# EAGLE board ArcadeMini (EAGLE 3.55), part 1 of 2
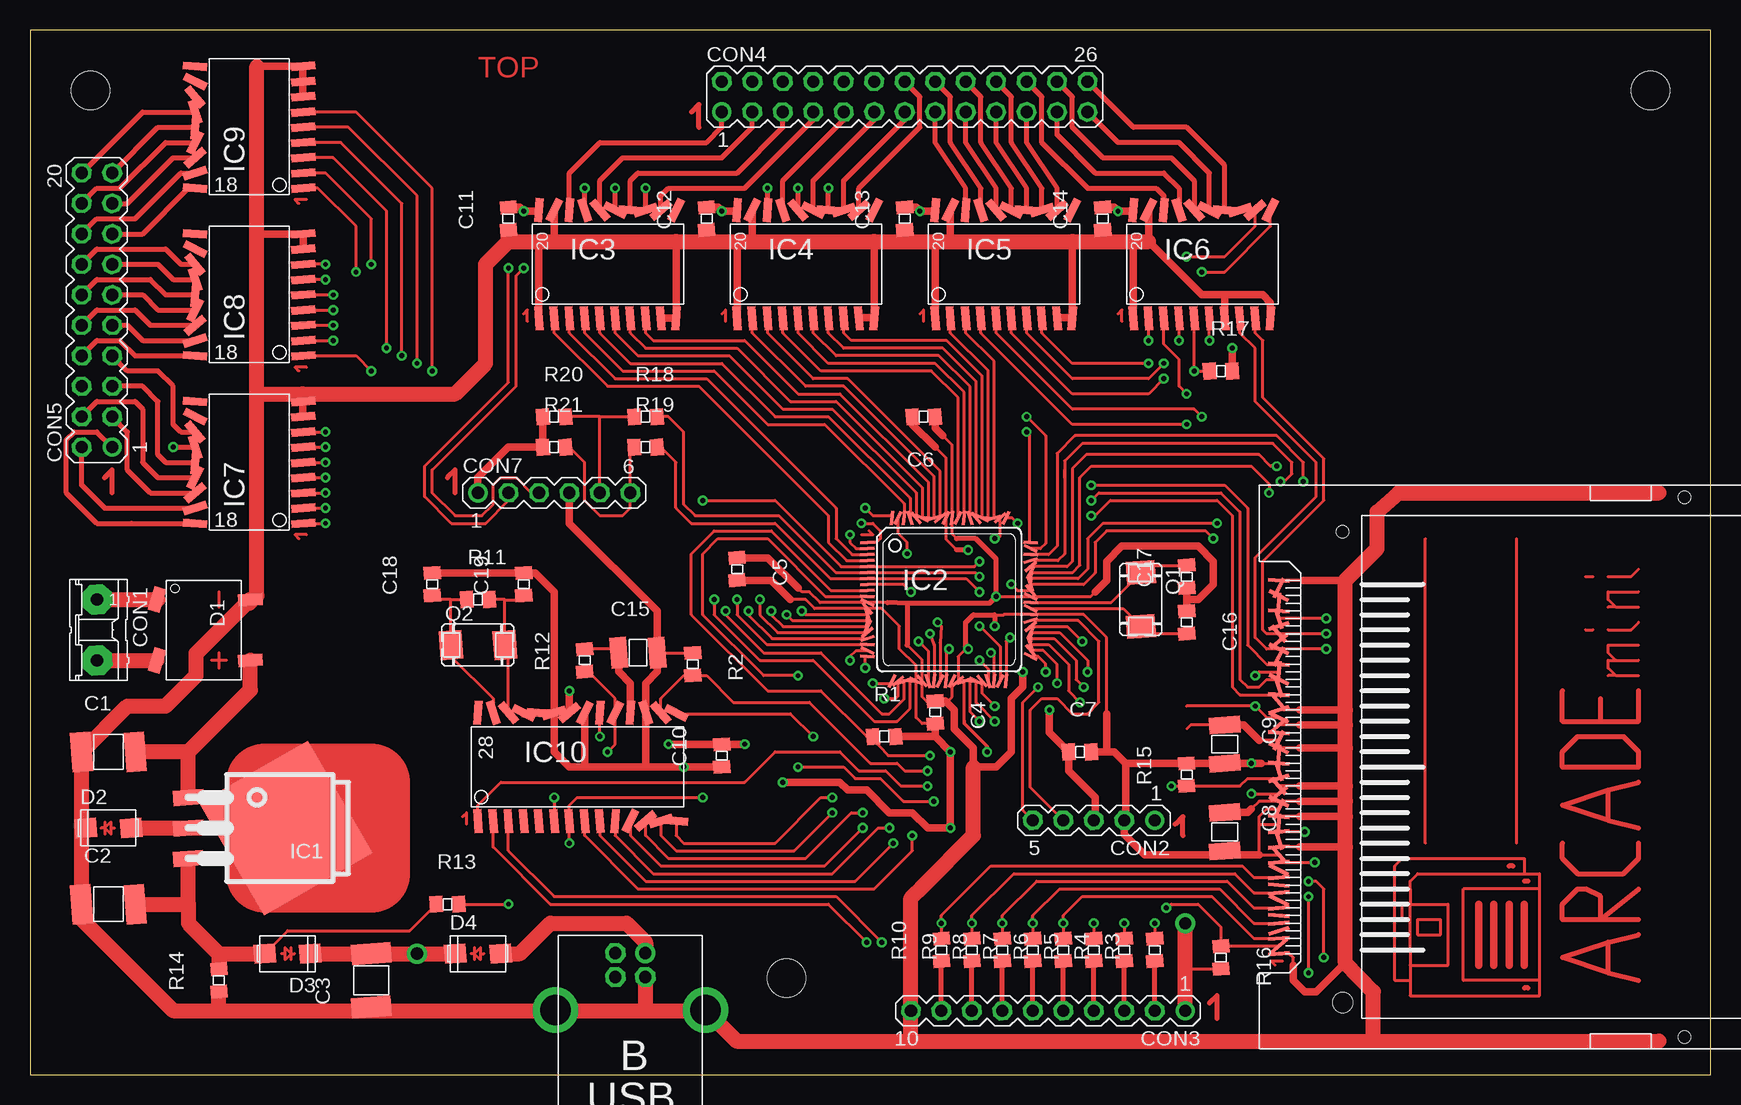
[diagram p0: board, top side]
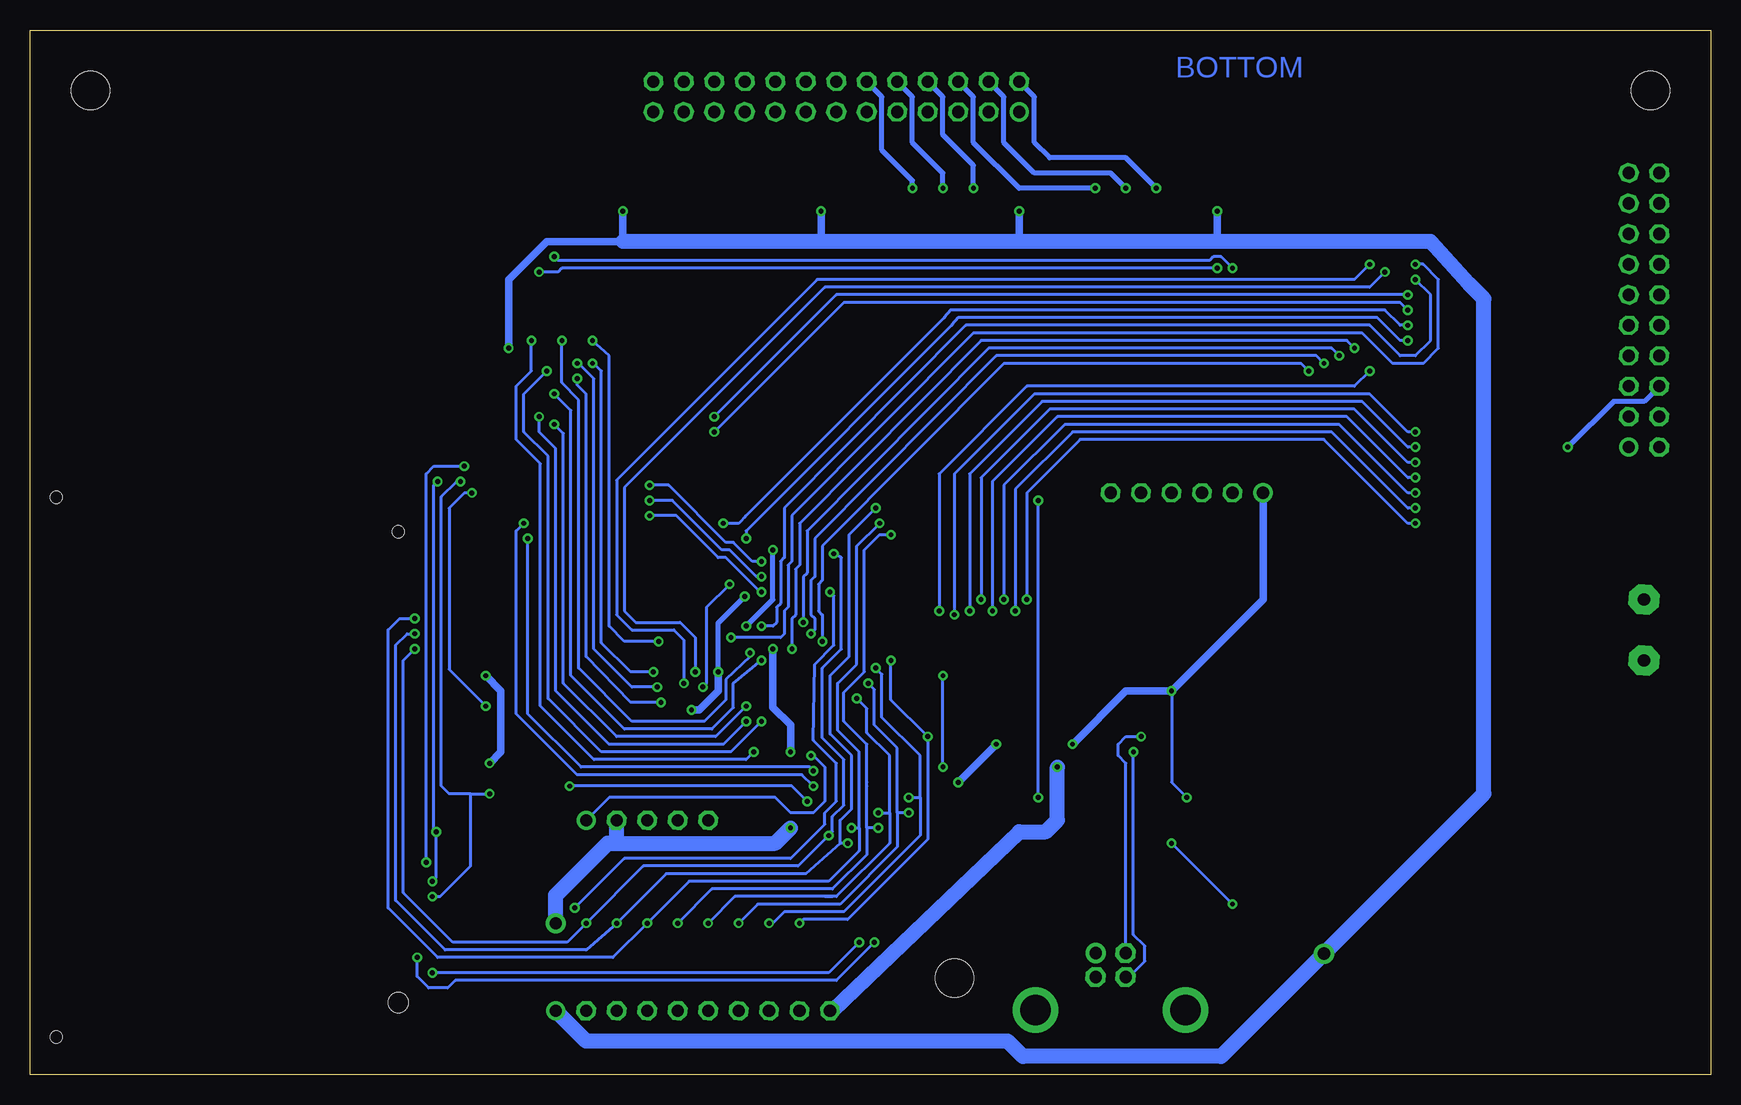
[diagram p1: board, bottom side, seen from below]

Size 140.08 x 87.12 mm. Coordinates in mm from the lower left corner, seen from the top.
Outline: 0,0 140.08,0 140.08,87.12 0,87.12 0,0
Copper layers used: Top, Bottom
Holes 3.2 mm at 5.04,82.08 135.04,82.08 63.04,8.08

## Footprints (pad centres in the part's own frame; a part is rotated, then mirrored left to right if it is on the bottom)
D-1812 = smd 1.702 x 3.302 rotated 4.4:  2.235,0 | smd 1.702 x 3.302 rotated 4.3:  -2.235,0
D-0805 = smd 1.092 x 1.397 rotated 4.4:  0.94,0 | smd 1.092 x 1.397 rotated 4.3:  -0.94,0
D-1210 = smd 1.397 x 2.591 rotated 4.4:  1.6,0 | smd 1.397 x 2.591 rotated 4.3:  -1.6,0
-FRM = smd 0.305 x 1.778 rotated 71.8:  -0.318,0.572 | smd 0.305 x 1.778 rotated 162:  -0.953,0.572 | smd 0.305 x 1.778 rotated 49.3:  -1.587,0.572 | smd 0.305 x 1.778 rotated 139.5:  -2.223,0.572 | smd 0.305 x 1.778 rotated 26.8:  -2.857,0.572 | smd 0.305 x 1.778 rotated 117:  -3.493,0.572 | smd 0.305 x 1.778 rotated 4.3:  -4.128,0.572;  -15.557,0.572 | smd 0.305 x 1.778 rotated 94.5:  -4.763,0.572 | smd 0.305 x 1.778 rotated 5:  -5.397,0.572 | smd 0.305 x 1.778 rotated 72:  -6.032,0.572 | smd 0.305 x 1.778 rotated 4.9:  -6.668,0.572 | smd 0.305 x 1.778 rotated 49.5:  -7.303,0.572 | smd 0.305 x 1.778 rotated 4.8:  -7.938,0.572 | smd 0.305 x 1.778 rotated 27:  -8.572,0.572 | smd 0.305 x 1.778 rotated 4.7:  -9.207,0.572;  -10.477,0.572;  15.557,0.572 | smd 0.305 x 1.778 rotated 4.5:  -9.842,0.572;  -13.018,0.572 | smd 0.305 x 1.778 rotated 206.9:  -11.113,0.572 | smd 0.305 x 1.778 rotated 4.6:  -11.748,0.572;  2.857,0.572 | smd 0.305 x 1.778 rotated 184.4:  -12.383,0.572 | smd 0.305 x 1.778 rotated 161.9:  -13.652,0.572 | smd 0.305 x 1.778 rotated 4.4:  -14.287,0.572;  8.572,0.572 | smd 0.305 x 1.778 rotated 139.4:  -14.922,0.572 | smd 0.305 x 1.778 rotated 116.9:  14.922,0.572 | smd 0.305 x 1.778 rotated 207.1:  14.287,0.572 | smd 0.305 x 1.778 rotated 94.4:  13.652,0.572 | smd 0.305 x 1.778 rotated 184.6:  13.018,0.572 | smd 0.305 x 1.778 rotated 71.9:  12.383,0.572 | smd 0.305 x 1.778 rotated 162.1:  11.748,0.572 | smd 0.305 x 1.778 rotated 49.4:  11.113,0.572 | smd 0.305 x 1.778 rotated 139.6:  10.477,0.572 | smd 0.305 x 1.778 rotated 26.9:  9.842,0.572 | smd 0.305 x 1.778 rotated 117.1:  9.207,0.572 | smd 0.305 x 1.778 rotated 94.6:  7.938,0.572 | smd 0.305 x 1.778 rotated 206.8:  7.303,0.572 | smd 0.305 x 1.778 rotated 72.1:  6.668,0.572 | smd 0.305 x 1.778 rotated 184.3:  6.032,0.572 | smd 0.305 x 1.778 rotated 49.6:  5.397,0.572 | smd 0.305 x 1.778 rotated 161.8:  4.763,0.572 | smd 0.305 x 1.778 rotated 27.1:  4.128,0.572 | smd 0.305 x 1.778 rotated 139.3:  3.493,0.572 | smd 0.305 x 1.778 rotated 116.8:  2.223,0.572 | smd 0.305 x 1.778 rotated 207:  1.587,0.572 | smd 0.305 x 1.778 rotated 94.3:  0.953,0.572 | smd 0.305 x 1.778 rotated 184.5:  0.318,0.572 | hole 1.676: -19.625,-4.75 | hole 1.016: 19.625,-4.75; 22.5,-33.25; -22.5,-33.25
N-BIG2 = drill 1.016 pad 2.54 octagon:  -2.54,0;  2.54,0
N-5-1 = drill 1.016 pad 1.6 round:  -5.08,0 | drill 1.016 pad 1.6 octagon:  -2.54,0;  0,0;  2.54,0;  5.08,0
N-10-1 = drill 1.016 pad 1.6 round:  -11.43,0 | drill 1.016 pad 1.6 octagon:  -8.89,0;  -6.35,0;  -3.81,0;  -1.27,0;  1.27,0;  3.81,0;  6.35,0;  8.89,0;  11.43,0
N-13-2 = drill 1.016 pad 1.6 round:  -15.24,-1.27 | drill 1.016 pad 1.6 octagon:  -12.7,-1.27;  -10.16,-1.27;  -7.62,-1.27;  -5.08,-1.27;  -2.54,-1.27;  -15.24,1.27;  -12.7,1.27;  -10.16,1.27;  -7.62,1.27;  -5.08,1.27;  -2.54,1.27;  0,-1.27;  0,1.27;  2.54,-1.27;  5.08,-1.27;  7.62,-1.27;  10.16,-1.27;  12.7,-1.27;  15.24,-1.27;  2.54,1.27;  5.08,1.27;  7.62,1.27;  10.16,1.27;  12.7,1.27;  15.24,1.27
N-10-2 = drill 1.016 pad 1.6 round:  -11.43,-1.27 | drill 1.016 pad 1.6 octagon:  -8.89,-1.27;  -6.35,-1.27;  -3.81,-1.27;  -1.27,-1.27;  1.27,-1.27;  -11.43,1.27;  -8.89,1.27;  -6.35,1.27;  -3.81,1.27;  -1.27,1.27;  1.27,1.27;  3.81,-1.27;  6.35,-1.27;  3.81,1.27;  6.35,1.27;  8.89,-1.27;  8.89,1.27;  11.43,-1.27;  11.43,1.27
B-B = drill 1.016 pad 1.676 octagon:  1.25,-1;  -1.25,1;  1.25,1 | drill 1.016 pad 1.676 round:  -1.25,-1 | drill 2.54 pad 3.81 round:  6.25,3.75;  -6.25,3.75
N-6-1 = drill 1.016 pad 1.6 round:  -6.35,0 | drill 1.016 pad 1.6 octagon:  -3.81,0;  -1.27,0;  1.27,0;  6.35,0;  3.81,0
64RECT = smd 1.016 x 2.032 rotated 4:  -2.515,3.886 | smd 1.016 x 2.032 rotated 3.8:  2.54,3.886 | smd 1.016 x 2.032 rotated 73.2:  2.54,-3.886;  -2.54,-3.886
A = smd 1.8 x 1.6 rotated 4.3:  -1.9,0 | smd 1.8 x 1.6 rotated 4.4:  1.9,0
-263 = smd 2.54 x 1.27 rotated 4.4:  -1.27,0 | smd 2.54 x 1.27 rotated 4.5:  -1.27,2.54 | smd 2.54 x 1.27 rotated 4.3:  -1.27,-2.54 | smd 10.414 x 10.795 rotated 29.9:  -9.398,0
FP-80 = smd 0.25 x 1.2 rotated 26.9:  -4.75,-6.8 | smd 0.25 x 1.2 rotated 49.4:  -4.25,-6.8 | smd 0.25 x 1.2 rotated 71.9:  -3.75,-6.8 | smd 0.25 x 1.2 rotated 94.4:  -3.25,-6.8 | smd 0.25 x 1.2 rotated 116.9:  -2.75,-6.8 | smd 0.25 x 1.2 rotated 139.4:  -2.25,-6.8 | smd 0.25 x 1.2 rotated 161.9:  -1.75,-6.8 | smd 0.25 x 1.2 rotated 184.4:  -1.25,-6.8 | smd 0.25 x 1.2 rotated 206.9:  -0.75,-6.8 | smd 0.25 x 1.2 rotated 4.5:  -0.25,-6.8 | smd 0.25 x 1.2 rotated 27:  0.25,-6.8 | smd 0.25 x 1.2 rotated 49.5:  0.75,-6.8 | smd 0.25 x 1.2 rotated 72:  1.25,-6.8 | smd 0.25 x 1.2 rotated 94.5:  1.75,-6.8 | smd 0.25 x 1.2 rotated 117:  2.25,-6.8 | smd 0.25 x 1.2 rotated 139.5:  2.75,-6.8 | smd 0.25 x 1.2 rotated 162:  3.25,-6.8 | smd 0.25 x 1.2 rotated 184.5:  3.75,-6.8 | smd 0.25 x 1.2 rotated 207:  4.25,-6.8 | smd 0.25 x 1.2 rotated 4.6:  4.75,-6.8 | smd 1.2 x 0.25 rotated 27.1:  6.8,-4.75 | smd 1.2 x 0.25 rotated 49.6:  6.8,-4.25 | smd 1.2 x 0.25 rotated 72.1:  6.8,-3.75 | smd 1.2 x 0.25 rotated 94.6:  6.8,-3.25 | smd 1.2 x 0.25 rotated 117.1:  6.8,-2.75 | smd 1.2 x 0.25 rotated 139.6:  6.8,-2.25 | smd 1.2 x 0.25 rotated 162.1:  6.8,-1.75 | smd 1.2 x 0.25 rotated 184.6:  6.8,-1.25 | smd 1.2 x 0.25 rotated 207.1:  6.8,-0.75 | smd 1.2 x 0.25 rotated 4.7:  6.8,-0.25;  6.8,4.75;  -6.8,2.75;  -6.8,2.25 | smd 1.2 x 0.25 rotated 27.2:  6.8,0.25 | smd 1.2 x 0.25 rotated 49.7:  6.8,0.75 | smd 1.2 x 0.25 rotated 72.2:  6.8,1.25 | smd 1.2 x 0.25 rotated 94.7:  6.8,1.75 | smd 1.2 x 0.25 rotated 117.2:  6.8,2.25 | smd 1.2 x 0.25 rotated 139.7:  6.8,2.75 | smd 1.2 x 0.25 rotated 162.2:  6.8,3.25 | smd 1.2 x 0.25 rotated 184.7:  6.8,3.75 | smd 1.2 x 0.25 rotated 207.2:  6.8,4.25 | smd 1.2 x 0.25 rotated 4.3:  -6.8,4.75;  -6.8,0.25 | smd 1.2 x 0.25 rotated 4.4:  -6.8,4.25;  -6.8,-4.75 | smd 1.2 x 0.25 rotated 4.5:  -6.8,3.75 | smd 1.2 x 0.25 rotated 4.6:  -6.8,3.25 | smd 1.2 x 0.25 rotated 4.8:  -6.8,1.75 | smd 1.2 x 0.25 rotated 4.9:  -6.8,1.25 | smd 1.2 x 0.25 rotated 5:  -6.8,0.75 | smd 1.2 x 0.25 rotated 26.8:  -6.8,-0.25 | smd 1.2 x 0.25 rotated 49.3:  -6.8,-0.75 | smd 1.2 x 0.25 rotated 71.8:  -6.8,-1.25 | smd 1.2 x 0.25 rotated 94.3:  -6.8,-1.75 | smd 1.2 x 0.25 rotated 116.8:  -6.8,-2.25 | smd 1.2 x 0.25 rotated 139.3:  -6.8,-2.75 | smd 1.2 x 0.25 rotated 161.8:  -6.8,-3.25 | smd 1.2 x 0.25 rotated 184.3:  -6.8,-3.75 | smd 1.2 x 0.25 rotated 206.8:  -6.8,-4.25 | smd 0.25 x 1.2 rotated 27.2:  4.75,6.8 | smd 0.25 x 1.2 rotated 49.7:  4.25,6.8 | smd 0.25 x 1.2 rotated 72.2:  3.75,6.8 | smd 0.25 x 1.2 rotated 94.7:  3.25,6.8 | smd 0.25 x 1.2 rotated 117.2:  2.75,6.8 | smd 0.25 x 1.2 rotated 139.7:  2.25,6.8 | smd 0.25 x 1.2 rotated 162.2:  1.75,6.8 | smd 0.25 x 1.2 rotated 184.7:  1.25,6.8 | smd 0.25 x 1.2 rotated 207.2:  0.75,6.8 | smd 0.25 x 1.2 rotated 4.8:  0.25,6.8 | smd 0.25 x 1.2 rotated 27.3:  -0.25,6.8 | smd 0.25 x 1.2 rotated 49.8:  -0.75,6.8 | smd 0.25 x 1.2 rotated 72.3:  -1.25,6.8 | smd 0.25 x 1.2 rotated 94.8:  -1.75,6.8 | smd 0.25 x 1.2 rotated 117.3:  -2.25,6.8 | smd 0.25 x 1.2 rotated 139.8:  -2.75,6.8 | smd 0.25 x 1.2 rotated 162.3:  -3.25,6.8 | smd 0.25 x 1.2 rotated 184.8:  -3.75,6.8 | smd 0.25 x 1.2 rotated 207.3:  -4.25,6.8 | smd 0.25 x 1.2 rotated 4.9:  -4.75,6.8
D-IC20 = smd 0.66 x 2.007 rotated 4.3:  -5.08,-4.496;  6.35,-4.496 | smd 0.66 x 2.007 rotated 4.4:  -3.81,-4.496;  -5.08,4.521 | smd 0.66 x 2.007 rotated 4.5:  -2.54,-4.496 | smd 0.66 x 2.007 rotated 4.6:  -1.27,-4.496 | smd 0.66 x 2.007 rotated 4.7:  0,-4.496;  1.27,-4.496 | smd 0.66 x 2.007 rotated 4.8:  2.54,-4.496 | smd 0.66 x 2.007 rotated 4.9:  3.81,-4.496 | smd 0.66 x 2.007 rotated 5:  5.08,-4.496 | smd 0.66 x 2.007 rotated 49.3:  5.08,4.521 | smd 0.66 x 2.007 rotated 26.8:  6.35,4.521 | smd 0.66 x 2.007 rotated 71.8:  3.81,4.521 | smd 0.66 x 2.007 rotated 94.3:  2.54,4.521 | smd 0.66 x 2.007 rotated 116.8:  1.27,4.521 | smd 0.66 x 2.007 rotated 139.3:  0,4.521 | smd 0.66 x 2.007 rotated 161.8:  -1.27,4.521 | smd 0.66 x 2.007 rotated 184.3:  -2.54,4.521 | smd 0.66 x 2.007 rotated 206.8:  -3.81,4.521
D-IC18 = smd 0.66 x 2.007 rotated 4.3:  -5.08,-4.496;  5.08,4.521 | smd 0.66 x 2.007 rotated 4.4:  -3.81,-4.496 | smd 0.66 x 2.007 rotated 4.5:  -2.54,-4.496 | smd 0.66 x 2.007 rotated 4.6:  -1.27,-4.496 | smd 0.66 x 2.007 rotated 4.7:  0,-4.496;  1.27,-4.496 | smd 0.66 x 2.007 rotated 4.8:  2.54,-4.496 | smd 0.66 x 2.007 rotated 4.9:  3.81,-4.496 | smd 0.66 x 2.007 rotated 5:  5.08,-4.496 | smd 0.66 x 2.007 rotated 49.3:  2.54,4.521 | smd 0.66 x 2.007 rotated 26.8:  3.81,4.521 | smd 0.66 x 2.007 rotated 71.8:  1.27,4.521 | smd 0.66 x 2.007 rotated 94.3:  0,4.521 | smd 0.66 x 2.007 rotated 116.8:  -1.27,4.521 | smd 0.66 x 2.007 rotated 139.3:  -2.54,4.521 | smd 0.66 x 2.007 rotated 161.8:  -3.81,4.521 | smd 0.66 x 2.007 rotated 184.3:  -5.08,4.521
D-IC28 = smd 0.66 x 2.007 rotated 4.3:  -7.62,-4.496;  3.81,-4.496 | smd 0.66 x 2.007 rotated 4.4:  -6.35,-4.496;  2.54,4.521 | smd 0.66 x 2.007 rotated 4.5:  -5.08,-4.496 | smd 0.66 x 2.007 rotated 4.6:  -3.81,-4.496 | smd 0.66 x 2.007 rotated 4.7:  -2.54,-4.496;  -1.27,-4.496 | smd 0.66 x 2.007 rotated 4.8:  0,-4.496 | smd 0.66 x 2.007 rotated 4.9:  1.27,-4.496 | smd 0.66 x 2.007 rotated 5:  2.54,-4.496 | smd 0.66 x 2.007 rotated 206.8:  3.81,4.521 | smd 0.66 x 2.007 rotated 26.9:  1.27,4.521 | smd 0.66 x 2.007 rotated 49.4:  0,4.521 | smd 0.66 x 2.007 rotated 71.9:  -1.27,4.521 | smd 0.66 x 2.007 rotated 94.4:  -2.54,4.521 | smd 0.66 x 2.007 rotated 116.9:  -3.81,4.521 | smd 0.66 x 2.007 rotated 139.4:  -5.08,4.521 | smd 0.66 x 2.007 rotated 161.9:  -6.35,4.521 | smd 0.66 x 2.007 rotated 184.4:  -7.62,4.521 | smd 0.66 x 2.007 rotated 139.3:  7.62,4.521 | smd 0.66 x 2.007 rotated 116.8:  8.89,4.521 | smd 0.66 x 2.007 rotated 161.8:  6.35,4.521 | smd 0.66 x 2.007 rotated 184.3:  5.08,4.521 | smd 0.66 x 2.007 rotated 26.8:  5.08,-4.496 | smd 0.66 x 2.007 rotated 49.3:  6.35,-4.496 | smd 0.66 x 2.007 rotated 71.8:  7.62,-4.496 | smd 0.66 x 2.007 rotated 94.3:  8.89,-4.496
-365 = smd 1.9 x 2.4 rotated 4.3:  -2.25,0 | smd 1.9 x 2.4 rotated 4.4:  2.25,0

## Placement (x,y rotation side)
C1  10uF  [D-1812]  6.53,26.94 0 top
C2  10uF  [D-1812]  6.53,14.24 0 top
C3  10uF  [D-1812]  28.44,7.89 90 top
C4  100nF  [D-0805]  75.43,30.23 270 top
C5  100nF  [D-0805]  58.92,42.18 270 top
C6  100nF  [D-0805]  74.48,54.88 180 top
C7  100nF  [D-0805]  87.5,26.94 0 top
C8  1.5uF  [D-1210]  99.56,20.27 270 top
C9  1.5uF  [D-1210]  99.56,27.58 270 top
C10  100nF  [D-0805]  57.65,26.62 90 top
C11  100nF  [D-0805]  39.87,71.39 90 top
C12  100nF  [D-0805]  56.38,71.39 90 top
C13  100nF  [D-0805]  72.89,71.39 90 top
C14  100nF  [D-0805]  89.4,71.39 90 top
C15  1.5uF  [D-1210]  50.66,35.2 0 top
C16  10pF  [D-0805]  96.4,37.73 270 top
C17  10pF  [D-0805]  96.4,41.55 90 top
C18  15pF  [D-0805]  33.52,40.91 90 top
C19  15pF  [D-0805]  41.14,40.91 90 top
CF1  CF-FRM  [-FRM]  104.64,25.67 90 top
CON1  CON-BIG2  [N-BIG2]  5.58,37.1 270 top
CON2  PROG  [N-5-1]  88.65,21.23 180 top
CON3  CON-10-1  [N-10-1]  84.84,5.35 180 top
CON4  CON-13-2  [N-13-2]  72.89,81.55 0 top
CON5  CON-10-2  [N-10-2]  5.58,63.77 90 top
CON6  USB-B  [B-B]  50.03,9.16 180 top
CON7  CON-6-1  [N-6-1]  43.68,48.53 0 top
D1  B40S  [64RECT]  14.47,37.1 270 top
D2  10MQ040N  [A]  6.53,20.59 0 top
D3  10MQ040N  [A]  21.45,10.11 180 top
D4  10MQ040N  [A]  37.33,10.11 0 top
IC1  LM2940S-5.0  [-263]  11.93,20.59 180 top
IC2  18F8520  [FP-80]  76.59,39.64 0 top
IC3  SMD-HC541  [D-IC20]  47.49,67.58 0 top
IC4  SMD-HC541  [D-IC20]  64,67.58 0 top
IC5  SMD-HC541  [D-IC20]  80.51,67.58 0 top
IC6  SMD-HC541  [D-IC20]  97.02,67.58 0 top
IC7  ULN2803LW  [D-IC18]  18.28,51.07 90 top
IC8  ULN2803LW  [D-IC18]  18.28,65.04 90 top
IC9  ULN2803LW  [D-IC18]  18.28,79.01 90 top
IC10  USBN9604  [D-IC28]  44.95,25.67 0 top
Q1  40MHz  [-365]  92.58,39.64 270 top
Q2  24MHz  [-365]  37.33,35.83 0 top
R1  10kOhm  [D-0805]  71.19,28.21 0 top
R2  10kOhm  [D-0805]  55.23,34.24 270 top
R3  10kOhm  [D-0805]  93.73,10.43 90 top
R4  10kOhm  [D-0805]  91.19,10.43 90 top
R5  10kOhm  [D-0805]  88.65,10.43 90 top
R6  10kOhm  [D-0805]  86.11,10.43 90 top
R7  10kOhm  [D-0805]  83.57,10.43 90 top
R8  10kOhm  [D-0805]  81.03,10.43 90 top
R9  10kOhm  [D-0805]  78.49,10.43 90 top
R10  10kOhm  [D-0805]  75.95,10.43 90 top
R11  1MOhm  [D-0805]  37.33,39.64 0 top
R12  1.5KOhm  [D-0805]  46.22,34.56 90 top
R13  10kOhm  [D-0805]  34.79,14.24 0 top
R14  10kOhm  [D-0805]  15.74,7.89 90 top
R15  10kOhm  [D-0805]  96.39,25.03 90 top
R16  10kOhm  [D-0805]  99.24,9.79 270 top
R17  10kOhm  [D-0805]  99.24,58.69 0 top
R18  10kOhm  [D-0805]  51.3,54.88 0 top
R19  10kOhm  [D-0805]  51.3,52.34 0 top
R20  10kOhm  [D-0805]  43.68,54.88 0 top
R21  10kOhm  [D-0805]  43.68,52.34 0 top

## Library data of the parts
C1-C19 CF1 CON1-CON7 D1-D4 IC1-IC10 Q1 Q2 R1-R21 = ArcadeMi

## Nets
CF_A0: CF1. IC2. IC10. R13.
CF_A1: CF1. IC2. R18.
CF_A2: CF1. IC2. R19.
CF_CD1/: CF1. IC2. R16.
CF_CE/: CF1. IC2.
CF_D0: CF1. IC2. IC6. IC10. R3.
CF_D1: CF1. IC2. IC6. IC10. R4.
CF_D2: CF1. IC2. IC10. R5.
CF_D3: CF1. IC2. IC10. R6.
CF_D4: CF1. IC2. IC10. R7.
CF_D5: CF1. IC2. IC10. R8.
CF_D6: CF1. IC2. IC10. R9.
CF_D7: CF1. IC2. IC10. R10.
CF_OE/: CF1. IC2. IC10.
CF_RDY: CF1. IC2. R15.
CF_RST/: CF1. IC2.
CF_UCS/: IC2. IC10.
CF_URST/: IC2. IC10. R2.
CF_WE/: CF1. IC2. IC10.
COL0: IC2. IC3.
COL1: IC2. IC3.
COL2: IC2. IC3.
COL3: IC2. IC3.
COL4: IC2. IC3.
COL5: IC2. IC3.
COL6: IC2. IC3.
COL7: IC2. IC4.
COL8: IC2. IC4.
COL9: IC2. IC4.
COL10: IC2. IC4.
COL11: IC2. IC4.
COL12: IC2. IC4.
COL13: IC2. IC4.
COL14: IC2. IC5.
COL15: IC2. IC5.
COL16: IC2. IC5.
COL17: IC2. IC5.
COL18: IC2. IC5.
COL19: IC2. IC5.
COL20: IC2. IC5.
COL21: IC2. IC6.
COL22: IC2. IC6.
COL23: IC2. IC6.
COL24: IC2. IC6. R17.
COL25: IC2. IC6.
GND: C1. C2. C3. C4. C5. C6. C7. C8. C9. C10. C11. C12. C13. C14. C15. C16. C17. C18. C19. CF1. CON2. CON3. CON6. CON7. D1. D2. IC2. IC3. IC4. IC5. IC6. IC7. IC8. IC9. IC10. R2. R14.
N$1: CON3. R7.
N$2: CON3. R6.
N$3: CON2. IC2. R1.
N$4: CON3. R5.
N$5: CON3. R4.
N$6: CON3. R3.
N$7: C16. IC2. Q1.
N$8: C17. IC2. Q1.
N$9: CON2. IC2.
N$10: CON2. IC2.
N$11: CON3. R8.
N$12: CON3. R9.
N$13: CON3. R10.
N$14: CON5. IC7.
N$15: CON5. IC7.
N$16: CON5. IC7.
N$17: CON5. IC7.
N$18: CON5. IC7.
N$19: CON5. IC7.
N$20: CON5. IC7.
N$21: CON5. IC8.
N$22: CON5. IC8.
N$23: CON5. IC8.
N$24: CON5. IC8.
N$25: CON5. IC8.
N$26: CON5. IC8.
N$27: CON5. IC8.
N$28: CON5. IC9.
N$29: CON5. IC9.
N$30: CON5. IC9.
N$31: CON5. IC9.
N$32: CON5. IC9.
N$33: CON5. IC9.
N$34: CON4. IC3.
N$35: CON4. IC3.
N$36: CON4. IC3.
N$37: CON4. IC3.
N$38: CON4. IC3.
N$39: CON4. IC3.
N$40: CON4. IC3.
N$41: CON4. IC4.
N$42: CON4. IC4.
N$43: CON4. IC4.
N$44: CON4. IC4.
N$45: CON4. IC4.
N$46: CON4. IC4.
N$47: CON4. IC4.
N$48: CON4. IC6.
N$49: CON4. IC6.
N$50: CON4. IC6.
N$51: CON4. IC6.
N$52: CON4. IC6.
N$53: CON4. IC5.
N$54: CON4. IC5.
N$55: CON4. IC5.
N$56: CON4. IC5.
N$57: CON4. IC5.
N$58: CON4. IC5.
N$59: CON4. IC5.
N$60: C19. IC10. Q2. R11.
N$61: C18. IC10. Q2. R11.
N$62: C15. IC10. R12.
N$63: D2. IC1.
N$64: CON6. IC10.
N$65: CON6. IC10. R12.
N$66: CON6. D4.
N$71: CON7. R19. R21.
N$72: CON7. R18. R20.
N$74: CON7. IC6.
N$75: CON7. IC6.
PWR1: CON1. D1.
PWR2: CON1. D1.
ROW0: IC2. IC7.
ROW1: IC2. IC7.
ROW2: IC2. IC7.
ROW3: IC2. IC7.
ROW4: IC2. IC7.
ROW5: IC2. IC7.
ROW6: IC2. IC7.
ROW7: IC2. IC8.
ROW8: IC2. IC8.
ROW9: IC2. IC8.
ROW10: IC2. IC8.
ROW11: IC2. IC8.
ROW12: IC2. IC8.
ROW13: IC2. IC8.
ROW14: IC2. IC9.
ROW15: IC2. IC9.
ROW16: IC2. IC9.
ROW17: IC2. IC9.
ROW18: IC2. IC9.
ROW19: IC2. IC9.
VCC: C3. C4. C5. C6. C7. C8. C9. C10. C11. C12. C13. C14. CF1. CON2. CON3. CON7. D3. D4. IC2. IC3. IC4. IC5. IC6. IC10. R1. R15. R16. R17. R20. R21.
VIN: C1. D1. IC1.
VOUT: C2. D3. IC1. R13. R14.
